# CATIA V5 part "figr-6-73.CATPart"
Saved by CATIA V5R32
Part number: Part2
Bounding box of the stored display mesh (mm): x -37.886 to 37.886, y -61.415 to 61.415, z 0 to 29
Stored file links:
  D:\PROJECTS\Project 2022\CATIA V5 6R 2022\Resources\Part Files\c06_catia_v5_6r2022_prt\figr-6-73.CATPart
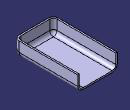
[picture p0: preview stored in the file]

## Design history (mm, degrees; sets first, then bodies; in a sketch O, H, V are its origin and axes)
Body1 (main body)
  Sketch1 on xy-plane, origin (0, 0, 0), H (1, 0, 0), V (0, 1, 0)
    line L1 (37.8862, 61.4155) -> (37.8862, -61.4155)
    line L2 (37.8862, -61.4155) -> (-37.8862, -61.4155)
    line L3 (-37.8862, -61.4155) -> (-37.8862, 61.4155)
    line L4 (-37.8862, 61.4155) -> (37.8862, 61.4155)
    vertical: L1 V, L3 V
    horizontal: L2 H, L4 H
    equidistance: L1 L3 O, L2 L4 O
  Pad1: profile Sketch1, direction (0, 0, 1), length 29
  Fillet1: radius 10, on edge [face of Pad1 | face of Pad1] (x5)
  Shell1: ExtOffset 0, Face (face of Pad1; face of Pad1), IntOffset 3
